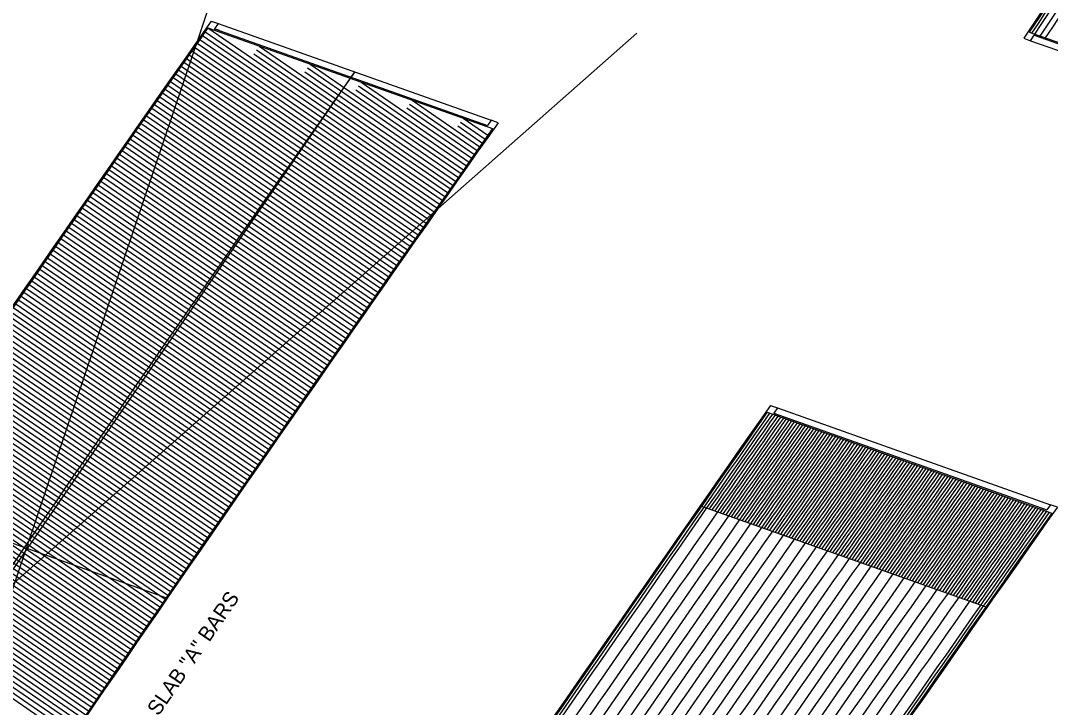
# Model space of a CAD drawing. Extents: x 2378999 to 2381348, y 331302 to 333122.
# Drawn here: x 2379768 to 2379905.9, y 332362.9 to 332454.8 of the extents above; entities that cross this region are included whole.
import ezdxf

# ---------------------------------------------------------------- set-up
doc = ezdxf.new("R2010")
doc.units = 0
for name, color, linetype in [('Arrowhead Terminators', 7, 'Continuous'), ('Mis Work Point CELL', 7, 'Continuous'), ('Old_Level_8', 7, 'Continuous'), ('P_SMU_Concrete_Barrier_Rail', 7, 'Continuous'), ('P_SMU_Mis_Long_Chord', 7, 'Continuous'), ('P_SMU_Rebar_B_Bar', 7, 'Continuous'), ('Plan Sheet CELL', 7, 'Continuous'), ('Scratch_Level_0', 7, 'Continuous'), ('Sup Concrete Slab Lines', 7, 'Continuous'), ('Text', 7, 'Continuous')]:
    doc.layers.add(name, color=color, linetype=linetype)

msp = doc.modelspace()

# ---------------------------------------------------------------- linework, layer by layer
at = {"layer": 'Arrowhead Terminators'}
for centre, radius, start, end in [((2385800.44, 328500.58), 7099.13, 145.763207, 146.167718), ((2385800.44, 328500.58), 7098.75, 145.762409, 146.166944), ((2385800.44, 328500.58), 7097.25, 145.759219, 146.163848), ((2385800.44, 328500.58), 7098, 146.041624, 146.165396), ((2385678.87, 328323.64), 7099.13, 144.933691, 145.338143), ((2385678.87, 328323.64), 7098.75, 144.932847, 145.337324), ((2385678.87, 328323.64), 7097.25, 144.929472, 145.334043), ((2385678.87, 328323.64), 7095.75, 144.926095, 145.330761), ((2385643.63, 328336.11), 7062.38, 144.850567, 144.975013), ((2385643.63, 328336.11), 7062, 144.849714, 144.974167), ((2385643.63, 328336.11), 7061.63, 144.848861, 144.97332), ((2385645.1, 328335.59), 7062.38, 144.850567, 144.975011), ((2385645.1, 328335.59), 7062, 144.849714, 144.974164), ((2385645.1, 328335.59), 7061.63, 144.848861, 144.973318), ((2385646.57, 328335.07), 7062.38, 144.850567, 144.975009), ((2385646.57, 328335.07), 7062, 144.849714, 144.974162), ((2385646.57, 328335.07), 7061.63, 144.848861, 144.973316), ((2385678.87, 328323.64), 7094.25, 144.922716, 145.327478), ((2385678.87, 328323.64), 7092.75, 144.919336, 145.324193), ((2385678.87, 328323.64), 7091.25, 144.915954, 145.320907), ((2385648.04, 328334.55), 7062.38, 144.850567, 144.975007), ((2385648.04, 328334.55), 7062, 144.849714, 144.97416), ((2385648.04, 328334.55), 7061.63, 144.848861, 144.973314), ((2385649.5, 328334.03), 7062.38, 144.850567, 144.975005), ((2385649.5, 328334.03), 7062, 144.849714, 144.974158), ((2385649.5, 328334.03), 7061.63, 144.848861, 144.973312), ((2385650.97, 328333.51), 7062.38, 144.850567, 144.975003), ((2385678.87, 328323.64), 7089.75, 144.912571, 145.317619), ((2385678.87, 328323.64), 7088.25, 144.909187, 145.31433), ((2385678.87, 328323.64), 7086.75, 144.9058, 145.31104), ((2385650.97, 328333.51), 7062, 144.849714, 144.974156), ((2385650.97, 328333.51), 7061.63, 144.848861, 144.97331), ((2385652.44, 328332.99), 7062.38, 144.850567, 144.975), ((2385652.44, 328332.99), 7062, 144.849714, 144.974154), ((2385652.44, 328332.99), 7061.63, 144.848861, 144.973308), ((2385653.91, 328332.47), 7062.38, 144.850567, 144.974998), ((2385653.91, 328332.47), 7062, 144.849714, 144.974152), ((2385653.91, 328332.47), 7061.63, 144.848861, 144.973306), ((2385678.87, 328323.64), 7085.25, 144.902413, 145.307748), ((2385678.87, 328323.64), 7083.75, 144.899024, 145.304454), ((2385655.38, 328331.95), 7062.38, 144.850567, 144.974996), ((2385655.38, 328331.95), 7062, 144.849714, 144.97415), ((2385655.38, 328331.95), 7061.63, 144.848861, 144.973304), ((2385656.85, 328331.43), 7062.38, 144.850567, 144.974994), ((2385656.85, 328331.43), 7062, 144.849714, 144.974148), ((2385656.85, 328331.43), 7061.63, 144.848861, 144.973302), ((2385658.31, 328330.91), 7062.38, 144.850567, 144.974992), ((2385658.31, 328330.91), 7062, 144.849714, 144.974146), ((2385678.87, 328323.64), 7082.25, 144.895633, 145.301159), ((2385678.87, 328323.64), 7080.75, 144.892241, 145.297863), ((2385678.87, 328323.64), 7079.25, 144.888848, 145.294565), ((2385658.31, 328330.91), 7061.63, 144.848861, 144.9733), ((2385659.78, 328330.39), 7062.38, 144.850567, 144.97499), ((2385659.78, 328330.39), 7062, 144.849714, 144.974144), ((2385659.78, 328330.39), 7061.63, 144.848861, 144.973298), ((2385661.25, 328329.87), 7062.38, 144.850567, 144.974988), ((2385661.25, 328329.87), 7062, 144.849714, 144.974142), ((2385661.25, 328329.87), 7061.63, 144.848861, 144.973296), ((2385662.72, 328329.35), 7062.38, 144.850567, 144.974986), ((2385678.87, 328323.64), 7077.75, 144.885453, 145.291266), ((2385678.87, 328323.64), 7076.25, 144.882056, 145.287965), ((2385678.87, 328323.64), 7074.75, 144.878658, 145.284663), ((2385662.72, 328329.35), 7062, 144.849714, 144.97414), ((2385662.72, 328329.35), 7061.63, 144.848861, 144.973294), ((2385664.19, 328328.83), 7062.38, 144.850567, 144.974984), ((2385664.19, 328328.83), 7062, 144.849714, 144.974138), ((2385664.19, 328328.83), 7061.63, 144.848861, 144.973292), ((2385665.65, 328328.31), 7062.38, 144.850567, 144.974982), ((2385665.65, 328328.31), 7062, 144.849714, 144.974136), ((2385665.65, 328328.31), 7061.63, 144.848861, 144.97329), ((2385678.87, 328323.64), 7073.25, 144.875259, 145.28136), ((2385678.87, 328323.64), 7071.75, 144.871858, 145.278055), ((2385667.12, 328327.8), 7062.38, 144.850567, 144.97498), ((2385667.12, 328327.8), 7062, 144.849714, 144.974134), ((2385667.12, 328327.8), 7061.63, 144.848861, 144.973287), ((2385668.59, 328327.28), 7062.38, 144.850567, 144.974978), ((2385668.59, 328327.28), 7062, 144.849714, 144.974132), ((2385668.59, 328327.28), 7061.63, 144.848861, 144.973285), ((2385670.06, 328326.76), 7062.38, 144.850567, 144.974976), ((2385670.06, 328326.76), 7062, 144.849714, 144.97413), ((2385678.87, 328323.64), 7070.25, 144.868455, 145.274748), ((2385678.87, 328323.64), 7068.75, 144.865051, 145.27144), ((2385678.87, 328323.64), 7067.25, 144.861645, 145.268131), ((2385670.06, 328326.76), 7061.63, 144.848861, 144.973283), ((2385671.53, 328326.24), 7062.38, 144.850567, 144.974974), ((2385671.53, 328326.24), 7062, 144.849714, 144.974128), ((2385671.53, 328326.24), 7061.63, 144.848861, 144.973281), ((2385673, 328325.72), 7062.38, 144.850567, 144.974972), ((2385673, 328325.72), 7062, 144.849714, 144.974126), ((2385673, 328325.72), 7061.63, 144.848861, 144.973279), ((2385674.47, 328325.2), 7062.38, 144.850567, 144.97497), ((2385678.87, 328323.64), 7065.75, 144.858238, 145.26482), ((2385678.87, 328323.64), 7064.25, 144.85483, 145.261508), ((2385678.87, 328323.64), 7062.75, 144.85142, 145.258194), ((2385674.47, 328325.2), 7062, 144.849714, 144.974124), ((2385674.47, 328325.2), 7061.63, 144.848861, 144.973277), ((2385675.93, 328324.68), 7062.38, 144.850567, 144.974968), ((2385675.93, 328324.68), 7062, 144.849714, 144.974122), ((2385675.93, 328324.68), 7061.63, 144.848861, 144.973275), ((2385677.4, 328324.16), 7062.38, 144.850567, 144.974966), ((2385677.4, 328324.16), 7062, 144.849714, 144.974119), ((2385677.4, 328324.16), 7061.63, 144.848861, 144.973273), ((2385678.87, 328323.64), 7061.25, 144.848008, 145.254879), ((2385678.87, 328323.64), 7060.88, 144.847155, 145.25405), ((2385678.87, 328323.64), 7062.38, 144.850567, 144.974964), ((2385678.87, 328323.64), 7062, 144.849714, 144.974117), ((2385678.87, 328323.64), 7061.63, 144.848861, 144.973271)]:
    msp.add_arc(centre, radius, start, end, dxfattribs=at)
at = {"layer": 'Mis Work Point CELL'}
msp.add_line((2379749.38, 332391.06), (2379787.69, 332377.5), dxfattribs=at)
at = {"layer": 'Old_Level_8'}
for p, q in [((2379792.77, 332453.3), (2379824.85, 332431.26)), ((2379793.13, 332453.81), (2379825.21, 332431.77)), ((2379791.69, 332451.76), (2379823.77, 332429.73)), ((2379792.05, 332452.28), (2379824.13, 332430.24)), ((2379792.41, 332452.79), (2379824.49, 332430.75)), ((2379790.97, 332450.74), (2379823.05, 332428.7)), ((2379791.33, 332451.25), (2379823.41, 332429.21)), ((2379799.25, 332450.36), (2379825.58, 332432.28)), ((2379799.61, 332450.88), (2379825.93, 332432.79)), ((2379799.96, 332451.39), (2379826.28, 332433.31)), ((2379789.9, 332449.21), (2379821.98, 332427.17)), ((2379790.26, 332449.72), (2379822.33, 332427.68)), ((2379790.62, 332450.23), (2379822.69, 332428.19)), ((2379806.79, 332448.97), (2379827.36, 332434.84)), ((2379788.82, 332447.67), (2379820.9, 332425.63)), ((2379789.18, 332448.18), (2379821.26, 332426.14)), ((2379789.54, 332448.69), (2379821.62, 332426.66)), ((2379806.08, 332447.94), (2379826.65, 332433.81)), ((2379806.44, 332448.46), (2379827.01, 332434.33)), ((2379788.11, 332446.65), (2379820.18, 332424.61)), ((2379788.46, 332447.16), (2379820.54, 332425.12)), ((2379813.62, 332446.56), (2379828.44, 332436.38)), ((2379787.03, 332445.11), (2379819.11, 332423.07)), ((2379787.39, 332445.62), (2379819.47, 332423.58)), ((2379787.75, 332446.13), (2379819.82, 332424.1)), ((2379812.91, 332445.53), (2379827.73, 332435.34)), ((2379813.27, 332446.04), (2379828.09, 332435.86)), ((2379785.96, 332443.57), (2379818.03, 332421.53)), ((2379786.31, 332444.09), (2379818.39, 332422.05)), ((2379786.67, 332444.6), (2379818.75, 332422.56)), ((2379820.09, 332443.63), (2379829.16, 332437.39)), ((2379820.45, 332444.14), (2379829.52, 332437.91)), ((2379785.24, 332442.55), (2379817.32, 332420.51)), ((2379785.6, 332443.06), (2379817.67, 332421.02)), ((2379819.74, 332443.11), (2379828.81, 332436.88)), ((2379784.17, 332441.01), (2379816.24, 332418.97)), ((2379784.52, 332441.52), (2379816.6, 332419.49)), ((2379784.88, 332442.04), (2379816.96, 332420)), ((2379826.57, 332440.69), (2379829.89, 332438.41)), ((2379826.92, 332441.21), (2379830.24, 332438.93)), ((2379827.28, 332441.72), (2379830.6, 332439.44)), ((2379783.09, 332439.47), (2379815.17, 332417.44)), ((2379783.45, 332439.99), (2379815.53, 332417.95)), ((2379783.81, 332440.5), (2379815.88, 332418.46)), ((2379782.02, 332437.94), (2379814.1, 332415.9)), ((2379782.38, 332438.45), (2379814.45, 332416.41)), ((2379782.73, 332438.96), (2379814.81, 332416.92)), ((2379781.3, 332436.91), (2379813.38, 332414.87)), ((2379781.66, 332437.42), (2379813.74, 332415.39)), ((2379780.23, 332435.37), (2379812.31, 332413.34)), ((2379780.59, 332435.89), (2379812.66, 332413.85)), ((2379780.95, 332436.4), (2379813.02, 332414.36)), ((2379779.16, 332433.84), (2379811.23, 332411.8)), ((2379779.52, 332434.35), (2379811.59, 332412.31)), ((2379779.87, 332434.86), (2379811.95, 332412.82)), ((2379778.44, 332432.81), (2379810.52, 332410.77)), ((2379778.8, 332433.32), (2379810.88, 332411.28)), ((2379777.37, 332431.27), (2379809.45, 332409.23)), ((2379777.73, 332431.78), (2379809.81, 332409.75)), ((2379778.09, 332432.3), (2379810.16, 332410.26)), ((2379776.3, 332429.73), (2379808.38, 332407.69)), ((2379776.66, 332430.24), (2379808.73, 332408.21)), ((2379777.02, 332430.76), (2379809.09, 332408.72)), ((2379775.59, 332428.71), (2379807.66, 332406.67)), ((2379775.94, 332429.22), (2379808.02, 332407.18)), ((2379774.52, 332427.17), (2379806.59, 332405.13)), ((2379774.87, 332427.68), (2379806.95, 332405.64)), ((2379775.23, 332428.19), (2379807.31, 332406.15)), ((2379773.45, 332425.63), (2379805.52, 332403.59)), ((2379773.8, 332426.14), (2379805.88, 332404.1)), ((2379774.16, 332426.65), (2379806.24, 332404.62)), ((2379772.73, 332424.6), (2379804.81, 332402.56)), ((2379773.09, 332425.11), (2379805.17, 332403.08)), ((2379771.66, 332423.06), (2379803.74, 332401.02)), ((2379772.02, 332423.57), (2379804.1, 332401.54)), ((2379772.38, 332424.09), (2379804.45, 332402.05)), ((2379770.6, 332421.52), (2379802.67, 332399.48)), ((2379770.95, 332422.03), (2379803.03, 332400)), ((2379771.31, 332422.55), (2379803.38, 332400.51)), ((2379769.88, 332420.49), (2379801.96, 332398.45)), ((2379770.24, 332421.01), (2379802.32, 332398.97)), ((2379768.82, 332418.95), (2379800.89, 332396.91)), ((2379769.17, 332419.46), (2379801.25, 332397.43)), ((2379769.53, 332419.98), (2379801.6, 332397.94)), ((2379767.75, 332417.41), (2379799.82, 332395.37)), ((2379768.1, 332417.92), (2379800.18, 332395.89)), ((2379768.46, 332418.44), (2379800.54, 332396.4)), ((2379766.68, 332415.87), (2379798.76, 332393.83)), ((2379767.04, 332416.38), (2379799.11, 332394.34)), ((2379767.39, 332416.9), (2379799.47, 332394.86)), ((2379765.97, 332414.84), (2379798.04, 332392.8)), ((2379766.32, 332415.35), (2379798.4, 332393.32)), ((2379764.9, 332413.3), (2379796.98, 332391.26)), ((2379765.26, 332413.81), (2379797.33, 332391.77)), ((2379765.61, 332414.33), (2379797.69, 332392.29)), ((2379763.84, 332411.76), (2379795.91, 332389.72)), ((2379764.19, 332412.27), (2379796.27, 332390.23)), ((2379764.55, 332412.78), (2379796.62, 332390.75)), ((2379763.12, 332410.73), (2379795.2, 332388.69)), ((2379763.48, 332411.24), (2379795.56, 332389.2)), ((2379762.06, 332409.19), (2379794.14, 332387.15)), ((2379762.41, 332409.7), (2379794.49, 332387.66)), ((2379762.77, 332410.21), (2379794.85, 332388.18)), ((2379760.99, 332407.64), (2379793.07, 332385.6)), ((2379761.35, 332408.16), (2379793.42, 332386.12)), ((2379761.7, 332408.67), (2379793.78, 332386.63)), ((2379760.28, 332406.61), (2379792.36, 332384.58)), ((2379760.64, 332407.13), (2379792.71, 332385.09)), ((2379759.22, 332405.07), (2379791.3, 332383.03)), ((2379759.57, 332405.58), (2379791.65, 332383.55)), ((2379759.93, 332406.1), (2379792.01, 332384.06)), ((2379758.16, 332403.53), (2379790.23, 332381.49)), ((2379758.51, 332404.04), (2379790.59, 332382)), ((2379758.86, 332404.56), (2379790.94, 332382.52)), ((2379757.45, 332402.5), (2379789.52, 332380.46)), ((2379757.8, 332403.01), (2379789.88, 332380.97)), ((2379756.38, 332400.95), (2379788.46, 332378.91)), ((2379756.74, 332401.47), (2379788.81, 332379.43)), ((2379757.09, 332401.98), (2379789.17, 332379.94)), ((2379755.32, 332399.41), (2379787.4, 332377.37)), ((2379755.67, 332399.92), (2379787.75, 332377.89)), ((2379756.03, 332400.44), (2379788.1, 332378.4)), ((2379754.61, 332398.38), (2379786.69, 332376.34)), ((2379754.97, 332398.89), (2379787.04, 332376.86)), ((2379753.55, 332396.83), (2379785.62, 332374.8)), ((2379753.9, 332397.35), (2379785.98, 332375.31)), ((2379754.26, 332397.86), (2379786.33, 332375.83)), ((2379752.49, 332395.29), (2379784.56, 332373.25)), ((2379752.84, 332395.8), (2379784.92, 332373.77)), ((2379753.19, 332396.32), (2379785.27, 332374.28)), ((2379751.78, 332394.26), (2379783.85, 332372.22)), ((2379752.13, 332394.77), (2379784.21, 332372.74)), ((2379750.72, 332392.71), (2379782.79, 332370.67)), ((2379751.07, 332393.23), (2379783.15, 332371.19)), ((2379751.43, 332393.74), (2379783.5, 332371.7)), ((2379749.66, 332391.17), (2379781.73, 332369.13)), ((2379750.01, 332391.68), (2379782.09, 332369.64)), ((2379750.36, 332392.2), (2379782.44, 332370.16)), ((2379748.95, 332390.13), (2379781.03, 332368.1)), ((2379749.3, 332390.65), (2379781.38, 332368.61)), ((2379747.89, 332388.59), (2379779.97, 332366.55)), ((2379748.24, 332389.1), (2379780.32, 332367.07)), ((2379748.6, 332389.62), (2379780.67, 332367.58)), ((2379746.83, 332387.04), (2379778.91, 332365)), ((2379747.18, 332387.56), (2379779.26, 332365.52)), ((2379747.54, 332388.07), (2379779.61, 332366.04)), ((2379746.12, 332386.01), (2379778.2, 332363.97)), ((2379746.48, 332386.53), (2379778.55, 332364.49)), ((2379745.06, 332384.46), (2379777.14, 332362.43)), ((2379745.42, 332384.98), (2379777.49, 332362.94)), ((2379745.77, 332385.49), (2379777.85, 332363.46)), ((2379744.01, 332382.92), (2379776.08, 332360.88)), ((2379744.36, 332383.43), (2379776.43, 332361.39)), ((2379744.71, 332383.95), (2379776.79, 332361.91)), ((2379743.3, 332381.88), (2379775.38, 332359.85)), ((2379743.65, 332382.4), (2379775.73, 332360.36)), ((2379742.59, 332380.85), (2379774.67, 332358.81)), ((2379742.95, 332381.37), (2379775.02, 332359.33))]:
    msp.add_line(p, q, dxfattribs=at)
at = {"layer": 'P_SMU_Concrete_Barrier_Rail'}
for p, q in [((2379793.56, 332454.72), (2379794.5, 332454.39)), ((2379794.5, 332454.39), (2379794, 332453.68)), ((2379794, 332453.68), (2379830.55, 332440.74)), ((2379794.65, 332453.45), (2379794, 332453.68)), ((2379902.34, 332452.43), (2379903.27, 332452.1)), ((2379903.27, 332452.1), (2379903.75, 332452.82)), ((2379903.75, 332452.82), (2379940.08, 332439.96)), ((2379904.4, 332452.59), (2379903.75, 332452.82)), ((2379829.89, 332440.97), (2379830.55, 332440.74)), ((2379831.04, 332441.45), (2379830.55, 332440.74)), ((2379831.98, 332441.12), (2379831.04, 332441.45)), ((2379868.43, 332403.28), (2379869.37, 332402.95)), ((2379869.37, 332402.95), (2379868.87, 332402.24)), ((2379868.87, 332402.24), (2379905.42, 332389.3)), ((2379869.53, 332402.01), (2379868.87, 332402.24)), ((2379905.91, 332390.01), (2379905.42, 332389.3)), ((2379906.85, 332389.68), (2379905.91, 332390.01)), ((2379904.76, 332389.54), (2379905.42, 332389.3))]:
    msp.add_line(p, q, dxfattribs=at)
for centre, radius, start, end in [((2385800.44, 328500.58), 7099.63, 144.926438, 146.177079), ((2385604, 328375.08), 7099.63, 144.926438, 146.177079), ((2385604, 328375.08), 7060.38, 144.837589, 146.095684), ((2385678.87, 328323.64), 7099.63, 144.926438, 146.177079), ((2385678.87, 328323.64), 7060.38, 144.837589, 146.095684)]:
    msp.add_arc(centre, radius, start, end, dxfattribs=at)
at = {"layer": 'P_SMU_Mis_Long_Chord'}
msp.add_arc((2385604, 328375.08), 7080, 144.882142, 146.136498, dxfattribs=at)
at = {"layer": 'P_SMU_Rebar_B_Bar'}
for p, q in [((2379794.5, 332454.39), (2379831.04, 332441.45)), ((2379903.27, 332452.1), (2379939.6, 332439.24)), ((2379869.37, 332402.95), (2379905.91, 332390.01))]:
    msp.add_line(p, q, dxfattribs=at)
at = {"layer": 'Plan Sheet CELL'}
msp.add_line((2379725, 332320.17), (2379812.77, 332447.92), dxfattribs=at)
at = {"layer": 'Scratch_Level_0'}
for p, q in [((2379793.13, 332453.81), (2379831.22, 332440.33)), ((2379903.08, 332453.23), (2379940.95, 332439.83)), ((2379868, 332402.37), (2379906.09, 332388.89)), ((2379859.2, 332389.81), (2379897.28, 332376.34))]:
    msp.add_line(p, q, dxfattribs=at)
for centre, radius, start, end in [((2385800.44, 328500.58), 7099.46, 144.934441, 146.168406), ((2385604, 328375.08), 7099.46, 144.934441, 146.168406), ((2385604, 328375.08), 7060.54, 144.846397, 146.087653), ((2385678.87, 328323.64), 7099.46, 144.934441, 146.168406), ((2385678.87, 328323.64), 7060.54, 144.846397, 146.087653)]:
    msp.add_arc(centre, radius, start, end, dxfattribs=at)
at = {"layer": 'Text'}
for p, q in [((2379737.17, 332290.49), (2379803.09, 332485.73)), ((2379850.55, 332453.13), (2379673.26, 332296.76))]:
    msp.add_line(p, q, dxfattribs=at)

# ---------------------------------------------------------------- texts
at = {"layer": 'Sup Concrete Slab Lines'}
msp.add_text('SLAB "A" BARS', height=2, rotation=55.5093, dxfattribs=at).set_placement((2379786.49, 332361.63))

doc.saveas('drawing.dxf')
